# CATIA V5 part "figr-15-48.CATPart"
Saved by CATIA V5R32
Part number: Part1
Bounding box of the stored display mesh (mm): x 0 to 69.121, y -21.475 to 20.775, z 0 to 47.185
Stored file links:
  D:\PROJECTS\Project 2022\CATIA V5 6R 2022\Resources\Part Files\c15_catia_v5_6r2022_prt\figr-15-48.CATPart
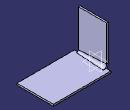
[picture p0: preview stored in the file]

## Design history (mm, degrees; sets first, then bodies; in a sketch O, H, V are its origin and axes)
SheetMetalParameters1: Thickness 2, BendRadius 4, KFactor 0.400515 {= log(min(100,max(20*SheetMetalParameters1.BendRadius,SheetMetalParameters1.Thickness)/SheetMetalParameters1.Thickness))/log(100)/2}, ReliefRadialLength 1, ReliefAxialLength 2, MinimumBendRadius 0
Body1 (main body)
  Sketch1 on xy-plane, origin (0, 0, 0), H (1, 0, 0), V (0, 1, 0)
    line L1 (2.4998, 20.7748) -> (69.1212, 20.7748)
    line L2 (69.1212, 20.7748) -> (69.1212, -21.4753)
    line L3 (69.1212, -21.4753) -> (2.4998, -21.4753)
    line L4 (2.4998, -21.4753) -> (2.4998, 20.7748)
    horizontal: L1 H, L3 H
    vertical: L2 V, L4 V
  Wall1: Thickness 2, Profile Sketch1
  Sketch2 on yz-plane, origin (0, 0, 0), H (0, 1, 0), V (0, 0, 1)
    line L1 (-17.3994, 47.1851) -> (15.4124, 47.1851)
    line L2 (15.4124, 47.1851) -> (15.4124, 3.5135)
    line L3 (15.4124, 3.5135) -> (-17.3994, 3.5135)
    line L4 (-17.3994, 3.5135) -> (-17.3994, 47.1851)
    horizontal: L1 H, L3 H
    vertical: L2 V, L4 V
  Wall2: Thickness 2, Profile Sketch2
  d_Bend1: Bend_Thickness 2, Bend_KFactor 0.36928 {= log(min(100,max(20*d_Bend1.Bend_KFactorRadius,SheetMetalParameters1.Thickness)/SheetMetalParameters1.Thickness))/log(100)/2}, Bend_FirstSupport Wall1, Bend_SecondSupport Wall2, Bend_KFactorRadius 3 {= ( d_Bend1.ConicalBendSurf_FirstRadius + d_Bend1.ConicalBendSurf_SecondRadius ) / 2.0}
